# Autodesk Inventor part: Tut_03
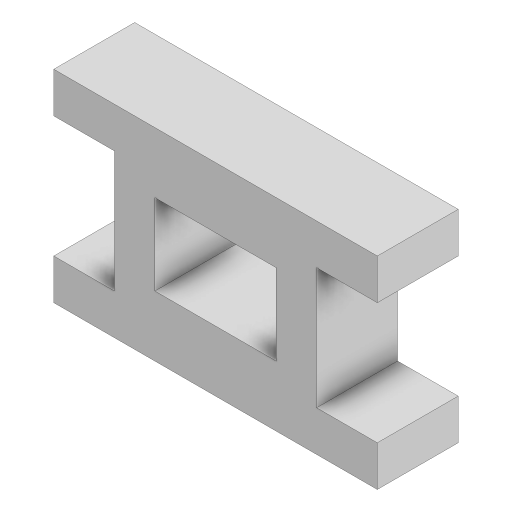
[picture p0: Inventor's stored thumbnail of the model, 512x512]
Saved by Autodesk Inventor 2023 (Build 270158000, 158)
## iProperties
Created: 2022-07
Part Number: Tut_03
Material: Generic
Document SubType Name: Modeling
Designer: LENOVO-CADCIM
Density: 1 g/cm^3
Appearance: Default
Author: LENOVO-CADCIM
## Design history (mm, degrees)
sketch "Sketch1"
  geometry: L1 (0, 0)-(40, 0); L2 (40, 0)-(40, 10); L3 (40, 10)-(25, 10); L4 (25, 10)-(25, 40); L5 (25, 40)-(40, 40); L6 (40, 40)-(40, 50); L7 (40, 50)-(-40, 50); L8 (-40, 50)-(-40, 40); L9 (-40, 40)-(-25, 40); L10 (-25, 40)-(-25, 10); L11 (-25, 10)-(-40, 10); L12 (-40, 10)-(-40, 0); L13 (-40, 0)-(0, 0); L14 (-15, 15)-(15, 15); L15 (15, 15)-(15, 35); L16 (15, 35)-(-15, 35); L17 (-15, 35)-(-15, 15)
  constraints: 34 end point, 13 perpendicular, 2 horizontal, 2 parallel, 1 collinear, 1 point on line
  dimensions: "d0" = 40 distance of L1.start L1.end; "d1" = 10 distance of L1.end L2.end; "d2" = 15 distance of L2.end L3.end; "d3" = 30 distance between parallel lines of L3 L5; "d4" = 15 distance of L4.end L5.end; "d5" = 10 distance of L5.end L6.end; "d6" = 10 distance of L7.end L8.end; "d7" = 15 distance of L8.end L9.end; "d8" = 30 distance of L9.end L10.end; "d9" = 15 distance of L10.end L11.end; "d11" = 20 distance of L16.end L14.start; "d12" = 30 distance of L14.start L14.end; "d13" = 10 distance between parallel lines of L4 L15; "d14" = 15 distance between parallel lines of L14 L1
extrude "Extrusion1" new body sketch "Sketch1" distance "d15" = 20; taper "d16" = 0 deg
body "Solid1"
